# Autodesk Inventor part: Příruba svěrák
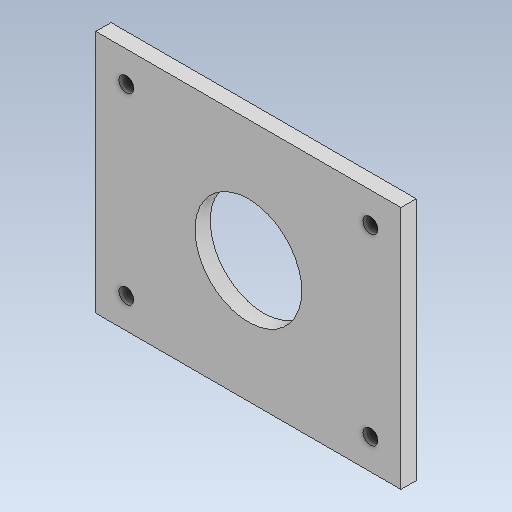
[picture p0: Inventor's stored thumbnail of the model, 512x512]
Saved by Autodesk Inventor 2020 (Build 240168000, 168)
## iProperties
Created: 2025-03
Part Number: Příruba svěrák
Material: Všeobecné
Document SubType Name: Modeling
Designer: doma
Density: 1 g/cm^3
Appearance: Výchozí
Mass: 34.8097 g
Surface Area: 165.826 cm^2
Volume: 34.8097 cm^3
Author: doma
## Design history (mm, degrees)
sketch "Náčrt1"
  geometry: L1 (-50, -40)-(50, -40); L2 (50, -40)-(50, 40); L3 (50, 40)-(-50, 40); L4 (-50, 40)-(-50, -40); L5 (-50, -40)-(50, 40); L6 (50, -40)-(-50, 40); C1 r 17.5 at (0, 0); 1 further point
  constraints: 12 end point, 2 midpoint, 2 parallel, 1 centre point, 1 coincident, 1 horizontal, 1 perpendicular
  dimensions: "d0" = 100 distance of L3.end L2.end; "d1" = 80 distance of L2.end L1.end; "d4" = 35 diameter of C1
extrude "Vysunutí1" new body sketch "Náčrt1" distance "d2" = 5; taper "d3" = 0 deg
sketch "Náčrt2"
  geometry: C1 r 3.5 at (-40, -30) reference; C2 r 3.5 at (40, -30) reference; C3 r 3.5 at (40, 30) reference; C4 r 3.5 at (-40, 30) reference; 5 further points
  constraints: 4 coincident
hole "Díra1" sketch "Náčrt2" at (-40, -30), (-40, 30), (40, 30), (40, -30) diameter "d5" = 4.917; stored, may be unused: countersink angle "d9" = 90 deg, drill point angle "d11" = 118 deg; dims "d6" = 12, "d7" = 4, "d8" = 2, "d10" = 17.1
node "Těleso1"
node "Referenční1"
node "Referenční2"
node "Referenční3"
node "Referenční4"
